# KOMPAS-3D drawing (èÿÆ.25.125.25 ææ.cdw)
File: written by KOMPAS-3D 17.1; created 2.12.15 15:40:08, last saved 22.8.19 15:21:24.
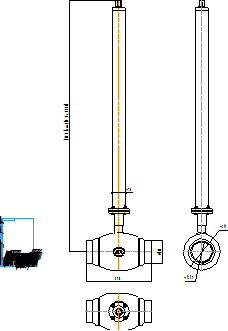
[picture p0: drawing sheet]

Sheet 1: A4, portrait

Title block, sheet 1: name: КШТ.25.125.25 С/С; sheets: 1; organisation: ООО "АДЛ Групп"; sheet format: A4; stored path: C:\Users\kka\KOMPAS_Work\Модели кранов для исследований\DN50\С удлинением\КШГ.32.050.40 СС ГЧ _ Шаровой кран БИВАЛ Ду50 Ру4 МПа редуцированный под приварку, с удлинением штока H=1100.cdw

Views: Вид 1, Проекционный вид 3
Referenced files in C:\Users\kka\KOMPAS_Work\Модели кранов для исследований\DN80\С удлинением\: КШТ.22.080.25 СС.a3d
Referenced files in C:\Users\kka\KOMPAS_Work\Модели кранов для исследований\DN150\С удлинением\: КШТ.22.150.25 СС.a3d, КШГ.35.125.25 СС Lстр600.a3d, КШГ.35.125.25 СС Lстр600.a3d!Деталь (локальная).m3d
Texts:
  Klimkovich
  ADL
  (от 410 до 5000)
  Рама для чертежей
  Лит-Масса-Масштаб
  Материал-Предприятие
  Масштаб
  Изм.
  Лист
  № докум.
  Подп.
  Дата
  Лит.
  Разраб.
  Пров.
  Т.контр.
  Листов
  Внимание! Данный продукт является объектом авторского права ООО «Торговый Дом АДЛ».
  Запрещается изменение, копирование, распространение
  (в том числе путем копирования на другие сайты и ресурсы в Интернете)
  или любое иное использование информации и объектов без предварительного
  согласия правообладателя (ООО «Торговый Дом АДЛ»).
  Н.контр.
  Утв.
  ООО "Торговый дом АДЛ"
  Изменение
  Номер документа
  Подпись
  Обозначение документа
  Наименование изделия
  Масса изделия по ГОСТ 2.109-73
  Порядковый номер листа
  Общее количество листов в документе
  Характер работы, выполненной лицом, подписавшим документ
  Наименование или индекс предприятия, выпускающего документ
  Инв. № подл.
  Подп. и дата
  Взам. инв. №
  Инв. № дубл.
  Инвентарный номер подлинника по ГОСТ 2.501-68
  Подпись принявшего подлинник в отдел технической документации
  Инвентарный номер подлинника, взамен которого выпущен данный подлинник
  Инвентарный номер дубликата по ГОСТ 2.502-68
  Подпись принявшего дубликат в отдел технической документации
  Справ. №
  Перв. примен.
  Обозначение документа, взамен или на основании которого выпущен данный документ
  Обозначение документа, в котором впервые записан данный документ
  Подпись лица, копировавшего чертеж
  Обозначение формата листа
  !Рама для чертежа
Dimensions and other numbers on the sheet: 76; 1500; 133; 390; 1:1; 1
